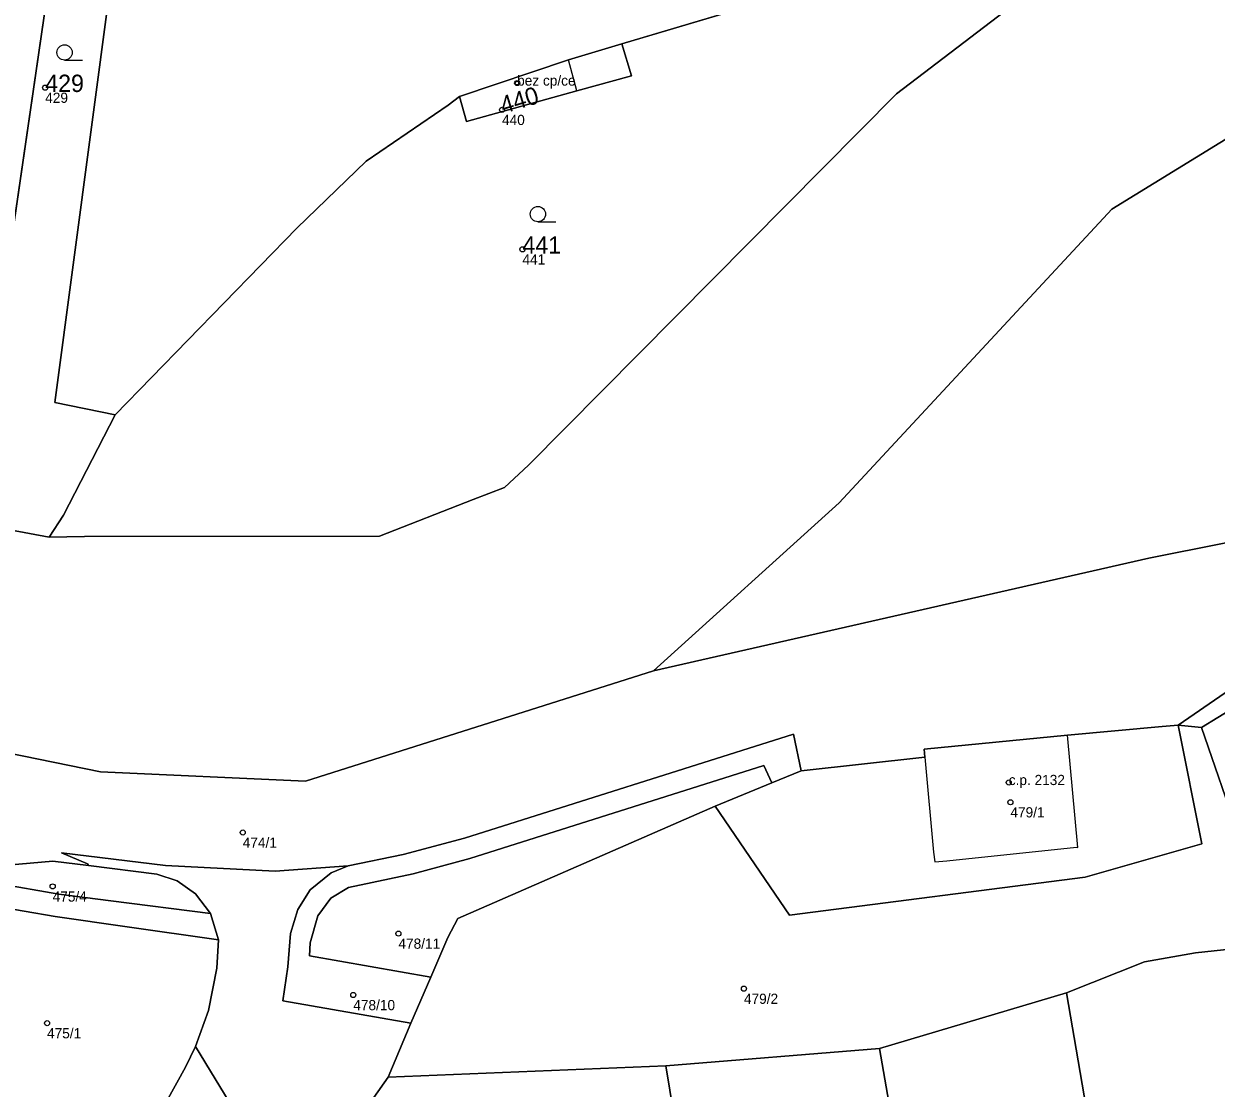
# Model space of a CAD drawing. Extents: x -878211 to -870363, y -1058464 to -1052522.
# Drawn here: x -874391.1 to -874274.3, y -1056425.6 to -1056321.3 of the extents above; entities that cross this region are included whole.
import ezdxf

# ---------------------------------------------------------------- set-up
doc = ezdxf.new("R2010")
doc.units = 0
for name, color, linetype in [('Definiční body', 7, 'Continuous'), ('Hranice parcel', 7, 'Continuous'), ('Parcelní čísla', 7, 'Continuous'), ('Polygon budovy', 7, 'Continuous'), ('Polygon parcely', 7, 'Continuous'), ('Vnitřní kresba', 7, 'Continuous'), ('Značky budov', 7, 'Continuous'), ('Značky kultur', 7, 'Continuous')]:
    doc.layers.add(name, color=color, linetype=linetype)

msp = doc.modelspace()

# ---------------------------------------------------------------- linework, layer by layer
at = {"layer": 'Definiční body'}
for centre in [(-874388.99, -1056327.54994), (-874342.76, -1056327.09994), (-874344.24, -1056329.71994), (-874342.24, -1056343.38994), (-874294.6, -1056395.63994), (-874294.44, -1056397.56994), (-874369.64, -1056400.53994), (-874388.26, -1056405.81994), (-874354.39, -1056410.43994), (-874358.81, -1056416.45994), (-874320.54, -1056415.83994), (-874388.81, -1056419.21994)]:
    msp.add_circle(centre, 0.25, dxfattribs=at)
at = {"layer": 'Hranice parcel'}
for p, q in [((-874396.34, -1056370.15), (-874384.87, -1056291.52)), ((-874311.81, -1056317.09), (-874332.51, -1056323.25)), ((-874332.51, -1056323.25), (-874337.74, -1056324.81)), ((-874337.74, -1056324.81), (-874348.41, -1056328.4))]:
    msp.add_line(p, q, dxfattribs=at)
for points in [[(-874382.15, -1056359.62), (-874388.04, -1056358.4), (-874382.65, -1056317.89), (-874379.48, -1056292.14)], [(-874388.61, -1056371.61), (-874385.14, -1056371.54), (-874356.24, -1056371.49), (-874347.06, -1056367.91), (-874344.01, -1056366.72), (-874341.65, -1056364.53), (-874305.59, -1056328.15), (-874284.45, -1056312)], [(-874336.9, -1056327.87), (-874331.57, -1056326.4), (-874332.51, -1056323.25)], [(-874329.41, -1056384.68), (-874311.2, -1056368.22), (-874284.49, -1056339.46), (-874263.34, -1056326.47), (-874262.52, -1056328.77)], [(-874348.41, -1056328.4), (-874347.73, -1056330.86), (-874336.9, -1056327.87)], [(-874348.41, -1056328.4), (-874349.53, -1056329.25), (-874357.55, -1056334.76), (-874364.33, -1056341.31), (-874382.15, -1056359.62)], [(-874388.61, -1056371.61), (-874387.19, -1056369.44), (-874382.15, -1056359.62)]]:
    msp.add_lwpolyline(points, dxfattribs=at)
at = {"layer": 'Polygon budovy'}
for points in [[(-874337.74, -1056324.81), (-874348.41, -1056328.4), (-874347.73, -1056330.86), (-874336.9, -1056327.87)], [(-874302.89, -1056392.38), (-874302.82, -1056393.14), (-874301.97, -1056402.45), (-874301.83, -1056403.41), (-874300.68, -1056403.31), (-874287.97, -1056401.99), (-874287.84, -1056402), (-874288.86, -1056391)]]:
    msp.add_lwpolyline(points, close=True, dxfattribs=at)
at = {"layer": 'Polygon parcely'}
for points in [[(-874396.34, -1056370.15), (-874384.87, -1056291.52), (-874382.69, -1056279.17), (-874389.52, -1056277.88), (-874390.55, -1056288.09), (-874395.91, -1056317.97), (-874398.91, -1056340.89), (-874402.03, -1056368.61)], [(-874388.61, -1056371.61), (-874387.19, -1056369.44), (-874382.15, -1056359.62), (-874388.04, -1056358.4), (-874382.65, -1056317.89), (-874379.48, -1056292.14), (-874378.04, -1056280.05), (-874382.69, -1056279.17), (-874384.87, -1056291.52), (-874396.34, -1056370.15)], [(-874305.59, -1056328.15), (-874284.45, -1056312), (-874285.09, -1056309.2), (-874306.98, -1056315.64), (-874311.81, -1056317.09), (-874332.51, -1056323.25), (-874331.57, -1056326.4), (-874336.9, -1056327.87), (-874347.73, -1056330.86), (-874348.41, -1056328.4), (-874349.53, -1056329.25), (-874357.55, -1056334.76), (-874364.33, -1056341.31), (-874382.15, -1056359.62), (-874387.19, -1056369.44), (-874388.61, -1056371.61), (-874385.14, -1056371.54), (-874356.24, -1056371.49), (-874347.06, -1056367.91), (-874344.01, -1056366.72), (-874341.65, -1056364.53)], [(-874347.73, -1056330.86), (-874336.9, -1056327.87), (-874331.57, -1056326.4), (-874332.51, -1056323.25), (-874337.74, -1056324.81), (-874348.41, -1056328.4)], [(-874238.99, -1056368.29), (-874255.22, -1056341.76), (-874262.52, -1056328.77), (-874263.34, -1056326.47), (-874284.49, -1056339.46), (-874311.2, -1056368.22), (-874329.41, -1056384.68), (-874280.88, -1056373.67), (-874258.43, -1056369.19)], [(-874278.02, -1056390.01), (-874275.72, -1056390.26), (-874272.52, -1056388.29), (-874268.28, -1056383.31)], [(-874361.01, -1056406.98), (-874359.27, -1056405.94), (-874352.93, -1056404.59), (-874347.41, -1056403.07), (-874318.59, -1056393.97), (-874317.8, -1056395.68), (-874314.94, -1056394.5), (-874315.68, -1056390.9), (-874347.93, -1056401.08), (-874353.93, -1056402.7), (-874359.31, -1056403.8), (-874360.99, -1056404.48), (-874363.04, -1056406.14), (-874364.23, -1056408.07), (-874364.97, -1056410.45), (-874365.23, -1056413.7), (-874365.71, -1056417.03), (-874353.17, -1056419.23), (-874351.21, -1056414.7), (-874363.09, -1056412.62), (-874363.04, -1056411.36), (-874362.3, -1056408.69)], [(-874275.72, -1056390.26), (-874278.02, -1056390.01), (-874275.69, -1056401.64), (-874287.11, -1056404.92), (-874316.07, -1056408.65), (-874323.36, -1056397.97), (-874348.58, -1056408.98), (-874349.54, -1056410.84), (-874351.21, -1056414.7), (-874353.17, -1056419.23), (-874355.4, -1056424.52), (-874328.21, -1056423.41), (-874307.26, -1056421.69), (-874288.94, -1056416.24), (-874281.31, -1056413.21), (-874276.32, -1056412.34), (-874269.29, -1056411.59), (-874268.35, -1056411.66)], [(-874314.94, -1056394.5), (-874317.8, -1056395.68), (-874323.36, -1056397.97), (-874316.07, -1056408.65), (-874287.11, -1056404.92), (-874275.69, -1056401.64), (-874278.02, -1056390.01), (-874279.56, -1056390.16), (-874288.86, -1056391), (-874302.89, -1056392.38), (-874302.82, -1056393.14)], [(-874351.21, -1056414.7), (-874349.54, -1056410.84), (-874348.58, -1056408.98), (-874323.36, -1056397.97), (-874317.8, -1056395.68), (-874318.59, -1056393.97), (-874347.41, -1056403.07), (-874352.93, -1056404.59), (-874359.27, -1056405.94), (-874361.01, -1056406.98), (-874362.3, -1056408.69), (-874363.04, -1056411.36), (-874363.09, -1056412.62)], [(-874413.76, -1056402.45), (-874399.99, -1056420.8), (-874384.79, -1056443.42), (-874382.93, -1056444.85), (-874382.6, -1056441.37), (-874382, -1056437.94), (-874381.27, -1056435.06), (-874380.43, -1056433.22), (-874379.13, -1056430.54), (-874375.26, -1056423.52), (-874374.27, -1056421.51), (-874373, -1056417.98), (-874372.17, -1056413.82), (-874372.03, -1056411.06), (-874380.96, -1056409.78), (-874388.01, -1056408.78), (-874394.12, -1056407.72), (-874399.07, -1056406.68)], [(-874372.79, -1056408.47), (-874374.26, -1056406.56), (-874376.05, -1056405.28), (-874378.06, -1056404.61), (-874384.74, -1056403.78), (-874388.24, -1056403.34), (-874398.64, -1056404.27), (-874393.67, -1056405.53), (-874387.64, -1056406.59), (-874382.56, -1056407.24)], [(-874285.32, -1056437.38), (-874283.19, -1056447.35), (-874283.6, -1056449.41), (-874279.38, -1056449.12), (-874278.64, -1056455.53), (-874273.97, -1056454.98), (-874273.03, -1056462.79), (-874265.57, -1056461.73), (-874269.29, -1056411.59), (-874276.32, -1056412.34), (-874281.31, -1056413.21), (-874288.94, -1056416.24)], [(-874285.17, -1056447.96), (-874284.95, -1056443.5), (-874285.32, -1056437.38), (-874288.94, -1056416.24), (-874307.26, -1056421.69), (-874301.92, -1056452.52), (-874285.06, -1056449.66)], [(-874307.26, -1056421.69), (-874328.21, -1056423.41), (-874322.92, -1056455.59), (-874323.82, -1056455.82), (-874323.42, -1056458.31), (-874321.4, -1056457.79), (-874316.56, -1056456.56), (-874301.92, -1056452.52)], [(-874322.92, -1056455.59), (-874328.21, -1056423.41), (-874355.4, -1056424.52), (-874358.83, -1056429.38), (-874347.77, -1056449.81), (-874334.9, -1056469.3), (-874331.21, -1056471.74), (-874321.3, -1056471.47), (-874323.42, -1056458.31), (-874323.82, -1056455.82)]]:
    msp.add_lwpolyline(points, close=True, dxfattribs=at)
for points in [[(-874165.06, -1056295.82), (-874167.76, -1056296.87), (-874168.88, -1056297.21), (-874168.94, -1056296.78), (-874169.88, -1056296.7), (-874173.09, -1056296.33), (-874175.94, -1056295.64), (-874215.04, -1056296.78), (-874223.82, -1056297.51), (-874254.81, -1056300.09), (-874261.43, -1056300.34), (-874268.45, -1056299.08), (-874270.66, -1056299.49), (-874272.3, -1056303.24), (-874270.58, -1056307.75), (-874284.45, -1056312), (-874305.59, -1056328.15), (-874341.65, -1056364.53), (-874344.01, -1056366.72), (-874347.06, -1056367.91), (-874356.24, -1056371.49), (-874385.14, -1056371.54), (-874388.61, -1056371.61), (-874396.34, -1056370.15)], [(-874382.65, -1056317.89), (-874388.04, -1056358.4), (-874382.15, -1056359.62), (-874364.33, -1056341.31), (-874357.55, -1056334.76), (-874349.53, -1056329.25), (-874348.41, -1056328.4), (-874337.74, -1056324.81), (-874332.51, -1056323.25), (-874311.81, -1056317.09)], [(-874407.9, -1056389.64), (-874383.57, -1056394.58), (-874363.5, -1056395.5), (-874329.41, -1056384.68), (-874311.2, -1056368.22), (-874284.49, -1056339.46), (-874263.34, -1056326.47)], [(-874258.43, -1056369.19), (-874280.88, -1056373.67), (-874329.41, -1056384.68), (-874363.5, -1056395.5), (-874383.57, -1056394.58), (-874407.9, -1056389.64)], [(-874398.64, -1056404.27), (-874388.24, -1056403.34), (-874384.74, -1056403.78), (-874384.84, -1056403.62), (-874387.39, -1056402.52), (-874377.2, -1056403.78), (-874366.46, -1056404.32), (-874359.31, -1056403.8), (-874353.93, -1056402.7), (-874347.93, -1056401.08), (-874315.68, -1056390.9), (-874314.94, -1056394.5), (-874302.82, -1056393.14), (-874302.89, -1056392.38), (-874288.86, -1056391), (-874279.56, -1056390.16), (-874278.02, -1056390.01), (-874268.28, -1056383.31)], [(-874272.52, -1056388.29), (-874275.72, -1056390.26), (-874268.35, -1056411.66)], [(-874358.83, -1056429.38), (-874355.4, -1056424.52), (-874353.17, -1056419.23), (-874365.71, -1056417.03), (-874365.23, -1056413.7), (-874364.97, -1056410.45), (-874364.23, -1056408.07), (-874363.04, -1056406.14), (-874360.99, -1056404.48), (-874359.31, -1056403.8), (-874366.46, -1056404.32), (-874377.2, -1056403.78), (-874387.39, -1056402.52), (-874384.84, -1056403.62), (-874384.74, -1056403.78), (-874378.06, -1056404.61), (-874376.05, -1056405.28), (-874374.26, -1056406.56), (-874372.79, -1056408.47), (-874372.03, -1056411.06), (-874372.17, -1056413.82), (-874373, -1056417.98), (-874374.27, -1056421.51), (-874364.19, -1056438.09)], [(-874394.12, -1056407.72), (-874388.01, -1056408.78), (-874380.96, -1056409.78), (-874372.03, -1056411.06), (-874372.79, -1056408.47), (-874382.56, -1056407.24), (-874387.64, -1056406.59), (-874393.67, -1056405.53)], [(-874364.19, -1056438.09), (-874374.27, -1056421.51), (-874375.26, -1056423.52), (-874379.13, -1056430.54)]]:
    msp.add_lwpolyline(points, dxfattribs=at)
at = {"layer": 'Vnitřní kresba'}
msp.add_line((-874336.9, -1056327.87), (-874337.74, -1056324.81), dxfattribs=at)
at = {"layer": 'Značky budov'}
msp.add_circle((-874342.7668, -1056327.09916), 0.175, dxfattribs=at)
at = {"layer": 'Značky kultur'}
for p, q in [((-874387.093, -1056324.85), (-874385.343, -1056324.85)), ((-874340.723, -1056340.69), (-874338.973, -1056340.69))]:
    msp.add_line(p, q, dxfattribs=at)
for centre in [(-874387.09286, -1056324.09981), (-874340.72286, -1056339.93981)]:
    msp.add_circle(centre, 0.75, dxfattribs=at)

# ---------------------------------------------------------------- texts
at = {"layer": 'Definiční body'}
for s, p in [('bez cp/ce', (-874342.76, -1056327.35)), ('429', (-874388.99, -1056329.039)), ('440', (-874344.24, -1056331.209)), ('441', (-874342.24, -1056344.879)), ('c.p. 2132', (-874294.6, -1056395.889)), ('479/1', (-874294.44, -1056399.059)), ('474/1', (-874369.64, -1056402.029)), ('475/4', (-874388.26, -1056407.309)), ('478/11', (-874354.39, -1056411.929)), ('479/2', (-874320.54, -1056417.329)), ('478/10', (-874358.81, -1056417.949)), ('475/1', (-874388.81, -1056420.709))]:
    msp.add_text(s, height=0.999996, dxfattribs=at).set_placement(p)
at = {"layer": 'Parcelní čísla'}
for s, p in [('429', (-874388.99, -1056327.975)), ('441', (-874342.24, -1056343.814))]:
    msp.add_text(s, height=1.699998, dxfattribs=at).set_placement(p)
msp.add_text('440', height=1.699998, rotation=17, dxfattribs=at).set_placement((-874344.115, -1056330.126))

doc.saveas('drawing.dxf')
